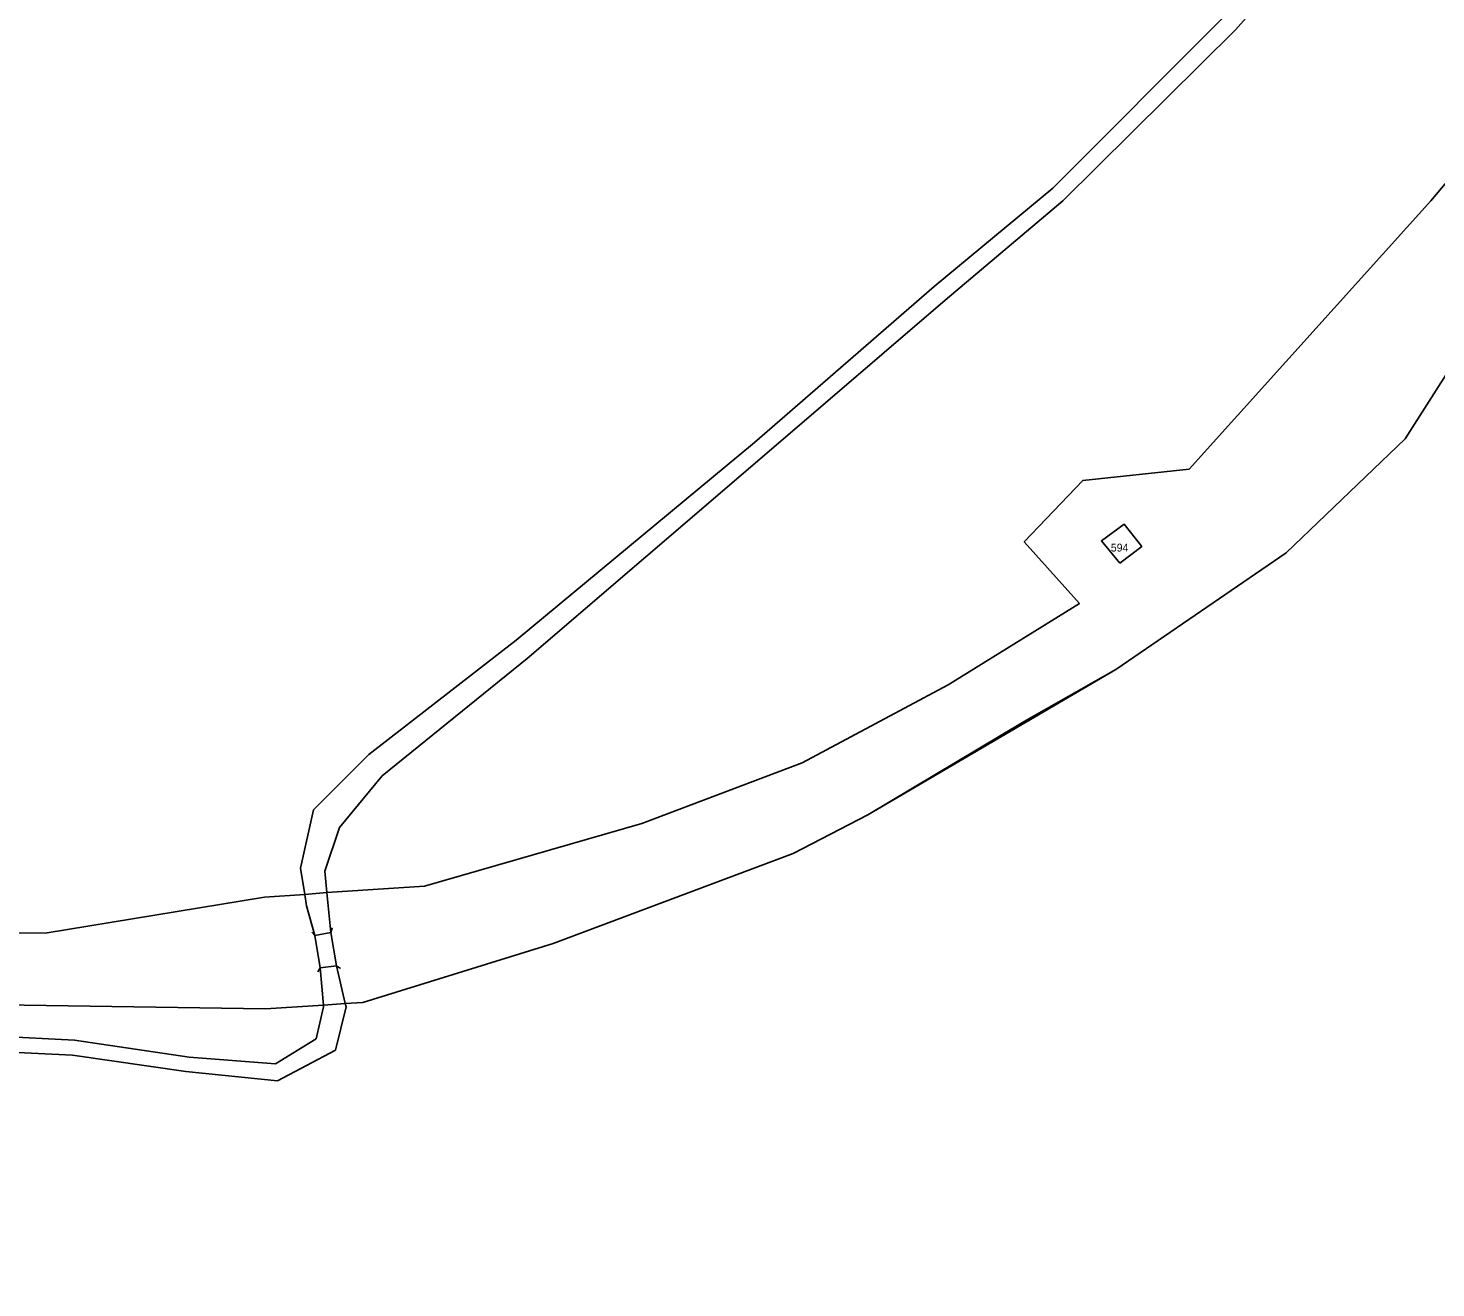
# Model space of a CAD drawing. Extents: x -520431 to -517205, y -1075927 to -1074013.
# Drawn here: x -519339.6 to -519035.6, y -1075095.5 to -1074823.4 of the extents above; entities that cross this region are included whole.
import ezdxf

# ---------------------------------------------------------------- set-up
doc = ezdxf.new("R2010")
doc.units = 0
for name, color, linetype in [('Hranice parcel', 7, 'Continuous'), ('Parcelní čísla', 7, 'Continuous'), ('Vnitřní kresba', 7, 'Continuous'), ('Vrstva 54', 7, 'Continuous')]:
    doc.layers.add(name, color=color, linetype=linetype)

msp = doc.modelspace()

# ---------------------------------------------------------------- linework, layer by layer
at = {"layer": 'Hranice parcel'}
for points in [[(-519700.87, -1075016.53), (-519625.74, -1075016), (-519537.55, -1075017.52), (-519461.14, -1075019.64), (-519417.45, -1075018.05), (-519395.71, -1075018.46), (-519335.89, -1075018.91), (-519288.52, -1075011.11), (-519279.85, -1075010.54), (-519275.05, -1075010.1), (-519253.96, -1075008.75), (-519207.07, -1074995.19), (-519172.44, -1074982.14), (-519140.89, -1074965.26), (-519112.56, -1074947.68), (-519124.49, -1074934.36), (-519111.85, -1074921.14), (-519088.9, -1074918.71), (-519036.69, -1074860.75), (-519005.51, -1074823.73)], [(-519924.37, -1075102.58), (-519892.38, -1075083.85), (-519867.1, -1075071.27), (-519819.84, -1075049.28), (-519782.45, -1075037.35), (-519747.25, -1075031.75), (-519705.46, -1075031.49), (-519632.74, -1075032.56), (-519553.06, -1075033.29), (-519504.34, -1075033.24), (-519467.55, -1075032.52), (-519378.37, -1075033.84), (-519288.33, -1075035.21), (-519275.81, -1075034.42), (-519271.08, -1075034.12), (-519267.29, -1075033.89), (-519226.23, -1075021.14), (-519174.38, -1075001.72), (-519158.26, -1074993.34), (-519124.51, -1074973.19), (-519104.71, -1074961.98), (-519067.92, -1074936.75), (-519042.21, -1074912.15), (-519022.03, -1074880.42)], [(-519103.84, -1074939.01), (-519107.81, -1074934.18), (-519102.89, -1074930.57), (-519099.11, -1074935.36), (-519103.84, -1074939.01)]]:
    msp.add_lwpolyline(points, dxfattribs=at)
at = {"layer": 'Vnitřní kresba'}
for p, q in [((-519051.77, -1074793.09), (-519078.85, -1074823.82)), ((-519081.6, -1074821.23), (-519118.29, -1074857.97)), ((-519078.85, -1074823.82), (-519116.18, -1074860.75)), ((-519118.29, -1074857.97), (-519143.92, -1074879.25)), ((-519116.18, -1074860.75), (-519141.55, -1074882.17)), ((-519143.92, -1074879.25), (-519182.75, -1074912.96)), ((-519141.55, -1074882.17), (-519180.6, -1074915.67)), ((-519182.75, -1074912.96), (-519234.21, -1074955.59)), ((-519180.6, -1074915.67), (-519231.8, -1074959.54)), ((-519234.21, -1074955.59), (-519265.97, -1074980.29)), ((-519231.8, -1074959.54), (-519263.15, -1074984.94)), ((-519265.97, -1074980.29), (-519277.96, -1074992.25)), ((-519263.15, -1074984.94), (-519272.35, -1074996.06)), ((-519277.96, -1074992.25), (-519280.76, -1075004.83)), ((-519272.35, -1074996.06), (-519275.49, -1075005.49)), ((-519280.76, -1075004.83), (-519279.85, -1075010.54)), ((-519275.49, -1075005.49), (-519275.05, -1075010.1)), ((-519279.85, -1075010.54), (-519279.47, -1075012.97)), ((-519275.05, -1075010.1), (-519274.22, -1075018.72)), ((-519277.66, -1075019.4), (-519279.47, -1075012.97)), ((-519278.33, -1075018.66), (-519277.66, -1075019.4)), ((-519277.66, -1075019.4), (-519274.22, -1075018.72)), ((-519277.66, -1075019.4), (-519276.54, -1075026.37)), ((-519273.93, -1075017.76), (-519274.22, -1075018.72)), ((-519274.22, -1075018.72), (-519272.98, -1075025.97)), ((-519276.54, -1075026.37), (-519272.98, -1075025.97)), ((-519272.98, -1075025.97), (-519271.08, -1075034.12)), ((-519272.15, -1075026.53), (-519272.98, -1075025.97)), ((-519277.01, -1075027.25), (-519276.54, -1075026.37)), ((-519275.81, -1075034.42), (-519276.54, -1075026.37)), ((-519277.37, -1075041.71), (-519275.78, -1075034.78)), ((-519275.78, -1075034.78), (-519275.81, -1075034.42)), ((-519270.91, -1075034.84), (-519273.22, -1075044.14)), ((-519271.08, -1075034.12), (-519270.91, -1075034.84)), ((-519363.56, -1075040.25), (-519329.54, -1075042.01)), ((-519329.98, -1075045.28), (-519363.84, -1075043.61)), ((-519329.54, -1075042.01), (-519304.79, -1075045.66)), ((-519286.17, -1075047.1), (-519277.37, -1075041.71)), ((-519273.22, -1075044.14), (-519285.75, -1075050.78)), ((-519305.53, -1075048.74), (-519329.98, -1075045.28)), ((-519304.79, -1075045.66), (-519286.17, -1075047.1)), ((-519285.75, -1075050.78), (-519305.53, -1075048.74))]:
    msp.add_line(p, q, dxfattribs=at)
at = {"layer": 'Vrstva 54'}
for points in [[(-519700.87, -1075016.53), (-519625.74, -1075016), (-519537.55, -1075017.52), (-519461.14, -1075019.64), (-519417.45, -1075018.05), (-519335.89, -1075018.91), (-519288.52, -1075011.11), (-519279.85, -1075010.54), (-519275.05, -1075010.1), (-519253.96, -1075008.75), (-519207.07, -1074995.19), (-519172.44, -1074982.14), (-519140.89, -1074965.26), (-519112.56, -1074947.68), (-519124.49, -1074934.36), (-519111.85, -1074921.14), (-519088.9, -1074918.71), (-519036.69, -1074860.75), (-519005.51, -1074823.73)], [(-519022.03, -1074880.42), (-519042.21, -1074912.15), (-519067.92, -1074936.75), (-519104.71, -1074961.98), (-519158.26, -1074993.34), (-519174.38, -1075001.72), (-519226.23, -1075021.14), (-519267.29, -1075033.89), (-519271.08, -1075034.12), (-519275.81, -1075034.42), (-519288.33, -1075035.21), (-519378.37, -1075033.84), (-519467.55, -1075032.52), (-519504.34, -1075033.24), (-519553.06, -1075033.29), (-519632.74, -1075032.56), (-519705.46, -1075031.49), (-519747.25, -1075031.75), (-519782.45, -1075037.35), (-519819.84, -1075049.28), (-519867.1, -1075071.27), (-519892.38, -1075083.85), (-519924.37, -1075102.58)]]:
    msp.add_lwpolyline(points, dxfattribs=at)

# ---------------------------------------------------------------- texts
at = {"layer": 'Parcelní čísla'}
msp.add_text('594', height=1.7, dxfattribs=at).set_placement((-519105.79, -1074936.48))

doc.saveas('drawing.dxf')
